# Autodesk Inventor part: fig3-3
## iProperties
Created: 2005-02
Part Number: fig3-3
Document SubType Name: Modeling
Designer: CADCIM
Manufacturer: Standard
Standards Organization: Custom
Author: CADCIM
